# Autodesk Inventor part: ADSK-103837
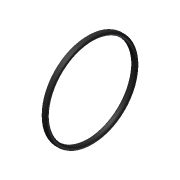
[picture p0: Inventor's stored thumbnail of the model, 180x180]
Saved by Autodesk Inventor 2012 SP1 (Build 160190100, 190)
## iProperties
Shininess: 20.0
Created: 2001-04
Part Number: ADSK-103837
Document SubType Name: Modeling
Designer: Administrator
Stock Number: ADSK-103837
Density: 1 g/cm^3
Material: Default
Density: 0.0
Volumn: 0.0
Area: 0.0
PropertySet Name: Model Information
Control State: 0
Master: False
Checked Out: False
Author: Administrator
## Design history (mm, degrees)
sketch "Sketch1"
  geometry: L1 (-15.841, 5.39)-(25.722, 5.39); L2 (-1.192, 30.79)-(-0.176, 30.79); L3 (-1.192, 28.758)-(-0.176, 28.758); A1 r 1.016 centre (-0.176, 29.774) between (-0.176, 28.758) and (-0.176, 30.79); A2 r 1.016 centre (-1.192, 29.774) between (-1.192, 30.79) and (-1.192, 28.758)
  constraints: 6 end point, 4 point on circle, 4 tangent, 2 centre point, 1 equal radius, 1 horizontal
  dimensions: "d0" = 2.032 diameter of A2; "d1" = 1.016 distance of A1.centre A2.centre; "d4" = 25.4 distance from line of L1 L2.end; "d6" = 23.368 distance between parallel lines of L1 L3 (derived)
revolve "Revolution1" sketch "Sketch1" stored, may be unused: angle "d5" = 90 deg
body "Solid1"
